Omron CX-Programmer project NuevoProyecto (CX-Programmer 9.50)

# PLC NewPLC1: CP1L-E EM

## Program P14_1 (cyclic task 0)
Local symbols
Etapa_0 10.00 BOOL
Etapa_1 10.01 BOOL
Etapa_10 10.10 BOOL
Etapa_11 10.11 BOOL
Etapa_12 10.12 BOOL
Etapa_13 10.13 BOOL
Etapa_14 10.14 BOOL
Etapa_15 10.15 BOOL
Etapa_16 11.00 BOOL
Etapa_2 10.02 BOOL
Etapa_3 10.03 BOOL
Etapa_4 10.04 BOOL
Etapa_5 10.05 BOOL
Etapa_6 10.06 BOOL
Etapa_7 10.07 BOOL
Etapa_8 10.08 BOOL
Etapa_9 10.09 BOOL
F 15.04 BOOL  ; Variable auxiliar
FBb1 15.02 BOOL  ; Flanco Bajada b1
FBb2 15.03 BOOL  ; Flanco Bajada b2
FSd1 15.00 BOOL  ; Flanco Subida d1
FSd2 15.01 BOOL  ; Flanco Subida d2
KD1 100.01 BOOL
KD2 100.03 BOOL
KI1 100.00 BOOL
KI2 100.02 BOOL
a_1 0.01 BOOL
a_2 0.04 BOOL
b_1 0.02 BOOL
b_2 0.05 BOOL
c 0.07 BOOL
d_1 0.03 BOOL
d_2 0.06 BOOL
m 0.00 BOOL

### Section Sección1_Programa_principal
; Etapas 0 ... 14

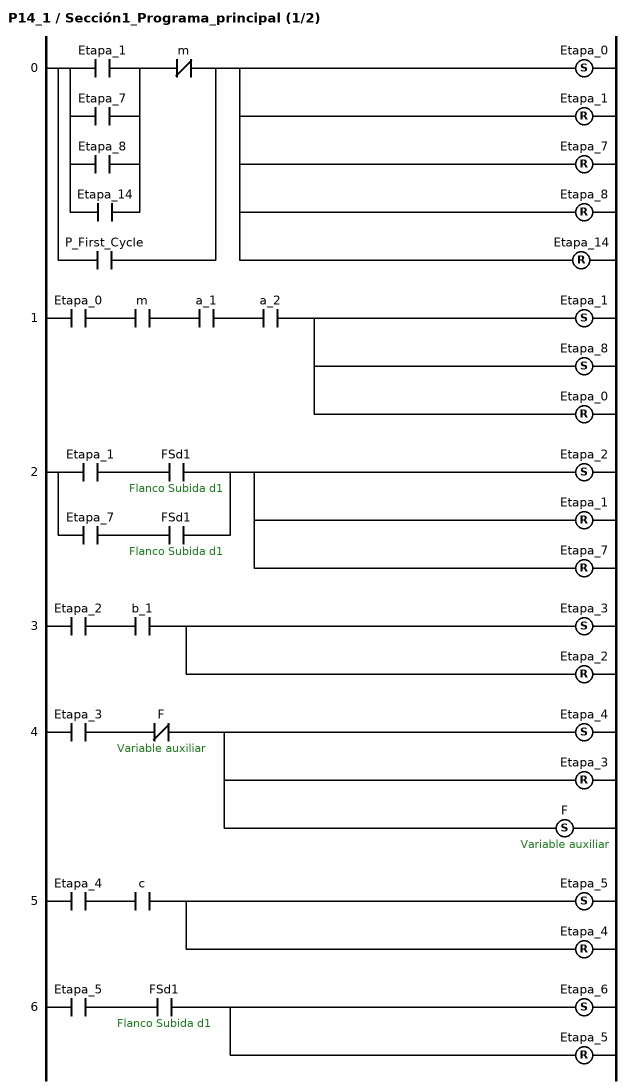
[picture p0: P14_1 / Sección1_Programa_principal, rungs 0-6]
; rung 0
LD Etapa_1
OR Etapa_7
OR Etapa_8
OR Etapa_14
ANDNOT m
OR P_First_Cycle
SET Etapa_0
RSET Etapa_1
RSET Etapa_7
RSET Etapa_8
RSET Etapa_14
; rung 1
LD Etapa_0
AND m
AND a_1
AND a_2
SET Etapa_1
SET Etapa_8
RSET Etapa_0
; rung 2
LD Etapa_1
AND FSd1  ; Flanco Subida d1
LD Etapa_7
AND FSd1  ; Flanco Subida d1
ORLD
SET Etapa_2
RSET Etapa_1
RSET Etapa_7
; rung 3
LD Etapa_2
AND b_1
SET Etapa_3
RSET Etapa_2
; rung 4
LD Etapa_3
ANDNOT F  ; Variable auxiliar
SET Etapa_4
RSET Etapa_3
SET F  ; Variable auxiliar
; rung 5
LD Etapa_4
AND c
SET Etapa_5
RSET Etapa_4
; rung 6
LD Etapa_5
AND FSd1  ; Flanco Subida d1
SET Etapa_6
RSET Etapa_5

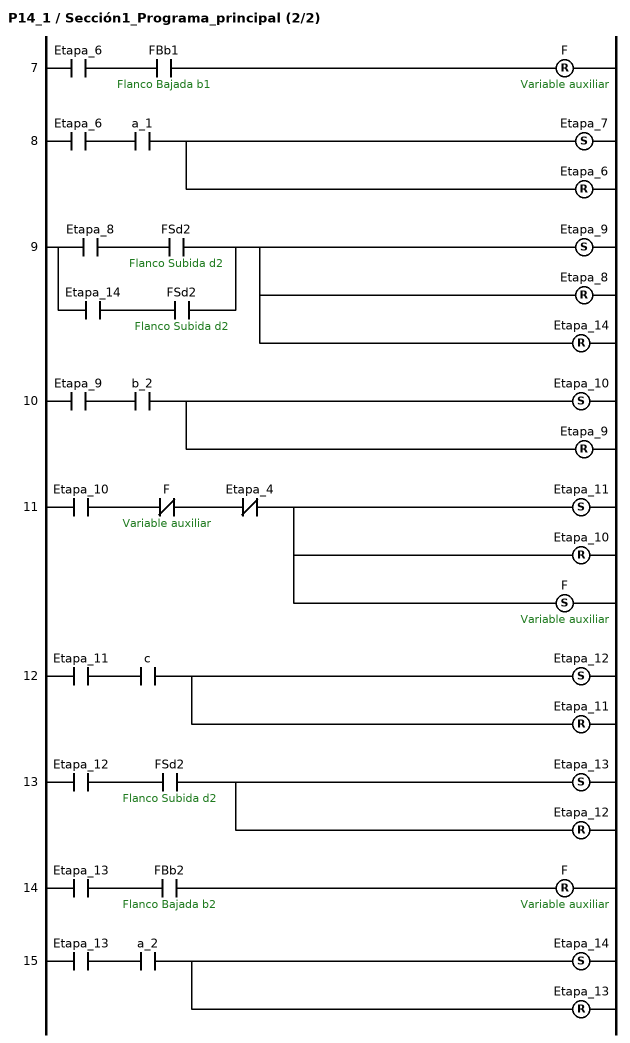
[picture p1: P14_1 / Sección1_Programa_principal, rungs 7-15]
; rung 7
LD Etapa_6
AND FBb1  ; Flanco Bajada b1
RSET F  ; Variable auxiliar
; rung 8
LD Etapa_6
AND a_1
SET Etapa_7
RSET Etapa_6
; rung 9
LD Etapa_8
AND FSd2  ; Flanco Subida d2
LD Etapa_14
AND FSd2  ; Flanco Subida d2
ORLD
SET Etapa_9
RSET Etapa_8
RSET Etapa_14
; rung 10
LD Etapa_9
AND b_2
SET Etapa_10
RSET Etapa_9
; rung 11
LD Etapa_10
ANDNOT F  ; Variable auxiliar
ANDNOT Etapa_4
SET Etapa_11
RSET Etapa_10
SET F  ; Variable auxiliar
; rung 12
LD Etapa_11
AND c
SET Etapa_12
RSET Etapa_11
; rung 13
LD Etapa_12
AND FSd2  ; Flanco Subida d2
SET Etapa_13
RSET Etapa_12
; rung 14
LD Etapa_13
AND FBb2  ; Flanco Bajada b2
RSET F  ; Variable auxiliar
; rung 15
LD Etapa_13
AND a_2
SET Etapa_14
RSET Etapa_13

### Section Sección2_Flancos

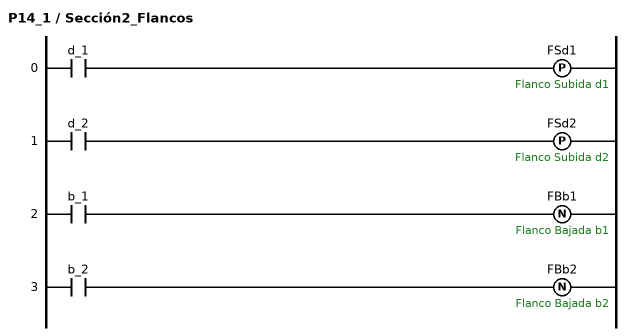
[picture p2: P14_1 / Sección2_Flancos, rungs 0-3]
; rung 0
LD d_1
DIFU(013) FSd1  ; Flanco Subida d1
; rung 1
LD d_2
DIFU(013) FSd2  ; Flanco Subida d2
; rung 2
LD b_1
DIFD(014) FBb1  ; Flanco Bajada b1
; rung 3
LD b_2
DIFD(014) FBb2  ; Flanco Bajada b2

### Section Sección3_Salidas
; Salidas

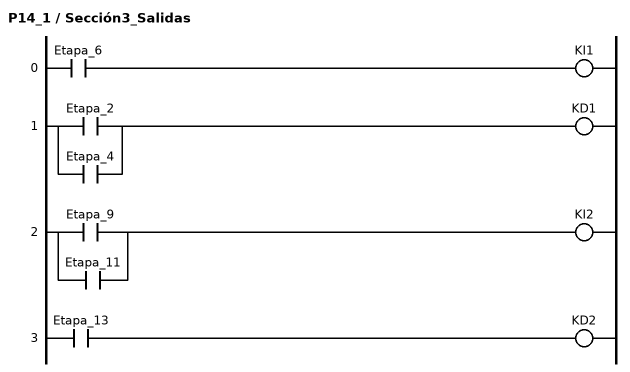
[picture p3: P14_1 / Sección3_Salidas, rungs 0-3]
; rung 0
LD Etapa_6
OUT KI1
; rung 1
LD Etapa_2
OR Etapa_4
OUT KD1
; rung 2
LD Etapa_9
OR Etapa_11
OUT KI2
; rung 3
LD Etapa_13
OUT KD2

### Section Sección4_END
; rung 0
END(001)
